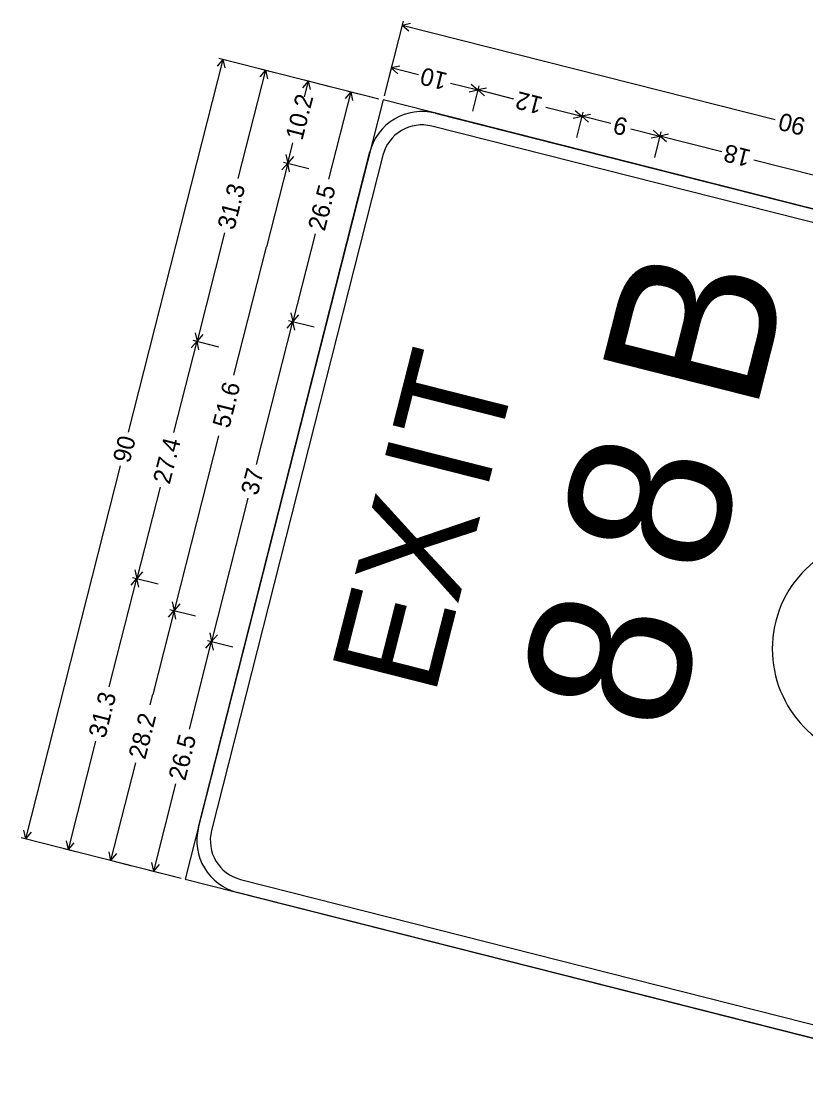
# Model space of a CAD drawing. Extents: x 670257 to 671518, y 737783 to 738188.
# Drawn here: x 670949.91 to 670960.88, y 737993.18 to 738007.95 of the extents above; entities that cross this region are included whole.
import ezdxf

# ---------------------------------------------------------------- set-up
doc = ezdxf.new("R2010")
doc.units = 0
doc.layers.add('R_SIGN', color=7, linetype='Continuous')

msp = doc.modelspace()

# ---------------------------------------------------------------- linework, layer by layer
at = {"layer": 'R_SIGN'}
for p, q in [((670955.251, 738007.954), (670954.987, 738006.91)), ((670955.356, 738007.92), (670955.236, 738007.894)), ((670960.452, 738006.571), (670955.236, 738007.894)), ((670955.329, 738007.814), (670955.236, 738007.894)), ((670951.412, 738002.202), (670952.735, 738007.418)), ((670952.655, 738007.325), (670952.735, 738007.418)), ((670952.676, 738007.433), (670954.912, 738006.866)), ((670952.762, 738007.298), (670952.735, 738007.418)), ((670955.1, 738007.357), (670955.009, 738007)), ((670955.205, 738007.324), (670955.085, 738007.298)), ((670952.947, 738005.75), (670953.332, 738007.266)), ((670953.251, 738007.173), (670953.332, 738007.266)), ((670953.272, 738007.282), (670953.63, 738007.191)), ((670953.358, 738007.146), (670953.332, 738007.266)), ((670955.466, 738007.201), (670955.085, 738007.298)), ((670955.178, 738007.217), (670955.085, 738007.298)), ((670953.848, 738007.022), (670953.928, 738007.115)), ((670953.868, 738007.13), (670954.226, 738007.04)), ((670953.872, 738006.895), (670953.928, 738007.115)), ((670953.954, 738006.995), (670953.928, 738007.115)), ((670955.916, 738007.087), (670956.296, 738006.99)), ((670956.203, 738007.071), (670956.296, 738006.99)), ((670956.312, 738007.05), (670956.221, 738006.692)), ((670956.417, 738007.017), (670956.296, 738006.99)), ((670954.214, 738005.74), (670954.524, 738006.964)), ((670954.444, 738006.871), (670954.524, 738006.964)), ((670954.465, 738006.979), (670954.822, 738006.888)), ((670954.55, 738006.844), (670954.524, 738006.964)), ((670956.176, 738006.964), (670956.296, 738006.99)), ((670956.799, 738006.863), (670956.296, 738006.99)), ((670956.39, 738006.91), (670956.296, 738006.99)), ((670954.971, 738006.851), (670952.206, 737995.946)), ((670965.876, 738004.085), (670954.971, 738006.851)), ((670957.248, 738006.749), (670957.75, 738006.622)), ((670955.698, 738006.666), (670965.876, 738004.085)), ((670957.63, 738006.595), (670957.75, 738006.622)), ((670957.657, 738006.702), (670957.75, 738006.622)), ((670957.766, 738006.681), (670957.675, 738006.324)), ((670957.871, 738006.648), (670957.75, 738006.622)), ((670958.154, 738006.519), (670957.75, 738006.622)), ((670957.844, 738006.541), (670957.75, 738006.622)), ((670965.83, 738003.903), (670955.652, 738006.484)), ((670958.437, 738006.448), (670958.841, 738006.345)), ((670958.748, 738006.426), (670958.841, 738006.345)), ((670958.721, 738006.319), (670958.841, 738006.345)), ((670958.856, 738006.405), (670958.765, 738006.047)), ((670958.961, 738006.371), (670958.841, 738006.345)), ((670959.706, 738006.126), (670958.841, 738006.345)), ((670958.934, 738006.265), (670958.841, 738006.345)), ((670952.39, 737996.673), (670954.787, 738006.124)), ((670953.637, 738005.966), (670953.708, 738006.25)), ((670954.969, 738006.077), (670952.572, 737996.627)), ((670953.577, 738005.981), (670953.935, 738005.891)), ((670953.577, 738005.981), (670953.935, 738005.891)), ((670953.61, 738006.086), (670953.637, 738005.966)), ((670953.717, 738006.059), (670953.637, 738005.966)), ((670954.969, 738006.077), (670954.969, 738006.077)), ((670960.157, 738006.011), (670961.022, 738005.792)), ((670953.637, 738005.966), (670953.339, 738004.793)), ((670953.556, 738005.873), (670953.637, 738005.966)), ((670953.663, 738005.846), (670953.637, 738005.966)), ((670952.754, 738004.99), (670952.37, 738003.474)), ((670954.02, 738004.975), (670953.709, 738003.751)), ((670952.884, 738002.999), (670953.339, 738004.793)), ((670953.65, 738003.766), (670954.007, 738003.675)), ((670953.65, 738003.766), (670954.007, 738003.675)), ((670953.683, 738003.871), (670953.709, 738003.751)), ((670953.79, 738003.844), (670953.709, 738003.751)), ((670953.201, 738001.747), (670953.709, 738003.751)), ((670953.629, 738003.658), (670953.709, 738003.751)), ((670953.736, 738003.631), (670953.709, 738003.751)), ((670952.046, 738002.195), (670952.37, 738003.474)), ((670952.289, 738003.381), (670952.37, 738003.474)), ((670952.31, 738003.489), (670952.668, 738003.398)), ((670952.31, 738003.489), (670952.668, 738003.398)), ((670952.343, 738003.594), (670952.37, 738003.474)), ((670952.45, 738003.567), (670952.37, 738003.474)), ((670952.396, 738003.354), (670952.37, 738003.474)), ((670952.668, 738002.149), (670951.751, 737998.533)), ((670951.293, 738001.729), (670949.97, 737996.513)), ((670951.852, 738001.433), (670951.528, 738000.154)), ((670953.082, 738001.276), (670952.573, 737999.273)), ((670951.501, 738000.274), (670951.528, 738000.154)), ((670951.608, 738000.247), (670951.528, 738000.154)), ((670951.143, 737998.638), (670951.528, 738000.154)), ((670951.447, 738000.061), (670951.528, 738000.154)), ((670951.468, 738000.169), (670951.826, 738000.079)), ((670951.554, 738000.034), (670951.528, 738000.154)), ((670952.023, 737999.827), (670952.049, 737999.707)), ((670952.129, 737999.8), (670952.049, 737999.707)), ((670951.969, 737999.614), (670952.049, 737999.707)), ((670951.989, 737999.722), (670952.347, 737999.631)), ((670952.075, 737999.587), (670952.049, 737999.707)), ((670952.547, 737999.393), (670952.573, 737999.273)), ((670952.654, 737999.366), (670952.573, 737999.273)), ((670952.263, 737998.048), (670952.573, 737999.273)), ((670952.493, 737999.179), (670952.573, 737999.273)), ((670952.514, 737999.288), (670952.872, 737999.197)), ((670952.6, 737999.152), (670952.573, 737999.273)), ((670951.714, 737998.386), (670951.751, 737998.533)), ((670950.951, 737997.878), (670950.566, 737996.362)), ((670951.508, 737997.573), (670951.162, 737996.21)), ((670952.069, 737997.283), (670951.759, 737996.059)), ((670949.91, 737996.528), (670952.146, 737995.961)), ((670949.943, 737996.633), (670949.97, 737996.513)), ((670950.05, 737996.606), (670949.97, 737996.513)), ((670950.506, 737996.377), (670950.864, 737996.286)), ((670950.54, 737996.482), (670950.566, 737996.362)), ((670950.646, 737996.455), (670950.566, 737996.362)), ((670951.103, 737996.226), (670951.46, 737996.135)), ((670951.136, 737996.331), (670951.162, 737996.21)), ((670951.243, 737996.304), (670951.162, 737996.21)), ((670951.699, 737996.074), (670952.057, 737995.984)), ((670951.732, 737996.179), (670951.759, 737996.059)), ((670951.839, 737996.152), (670951.759, 737996.059)), ((670952.206, 737995.946), (670963.11, 737993.18)), ((670952.979, 737995.943), (670963.157, 737993.362)), ((670952.979, 737995.943), (670952.979, 737995.943)), ((670963.11, 737993.18), (670952.933, 737995.761))]:
    msp.add_line(p, q, dxfattribs=at)
for centre, radius, start, end in [((670955.514, 738005.939), 0.75, 75.7686, 165.7688), ((670955.514, 738005.939), 0.562, 75.7686, 165.7688), ((670961.982, 737999.168), 1.568, 76.1684, 254.9793), ((670953.117, 737996.488), 0.75, 165.7688, 255.7684), ((670953.117, 737996.488), 0.562, 165.7688, 255.7684)]:
    msp.add_arc(centre, radius, start, end, dxfattribs=at)

# ---------------------------------------------------------------- texts
for s, height, rotation, p in [('10', 0.2461, 165.7688, (670955.886, 738007.221)), ('10.2', 0.2461, 75.7686, (670953.841, 738006.273)), ('12', 0.2461, 165.7688, (670957.218, 738006.884)), ('9', 0.246, 165.7688, (670958.408, 738006.582)), ('90', 0.2461, 165.7688, (670960.895, 738006.586)), ('18', 0.2461, 165.7688, (670960.128, 738006.146)), ('31.3', 0.2461, 75.7686, (670952.889, 738005.02)), ('26.5', 0.2461, 75.7686, (670954.154, 738005.004)), ('B', 2.25, 75.7686, (670960.169, 738002.429)), ('T', 1.5, 75.7686, (670956.549, 738001.885)), ('51.6', 0.2461, 75.7686, (670952.82, 738002.245)), ('90', 0.2461, 75.7686, (670951.427, 738001.758)), ('27.4', 0.2461, 75.7686, (670951.987, 738001.462)), ('I', 1.5, 75.7686, (670956.409, 738001.333)), ('8', 2.25, 75.7686, (670959.588, 738000.139)), ('37', 0.2461, 75.7686, (670953.216, 738001.305)), ('X', 1.5, 75.7686, (670956.011, 737999.763)), ('E', 1.5, 75.7686, (670955.686, 737998.483)), ('8', 2.25, 75.7686, (670959.03, 737997.937)), ('31.3', 0.2461, 75.7686, (670951.085, 737997.907)), ('28.2', 0.2461, 75.7686, (670951.644, 737997.611)), ('26.5', 0.2461, 75.7686, (670952.203, 737997.313))]:
    msp.add_text(s, height=height, rotation=rotation, dxfattribs=at).set_placement(p)

doc.saveas('drawing.dxf')
